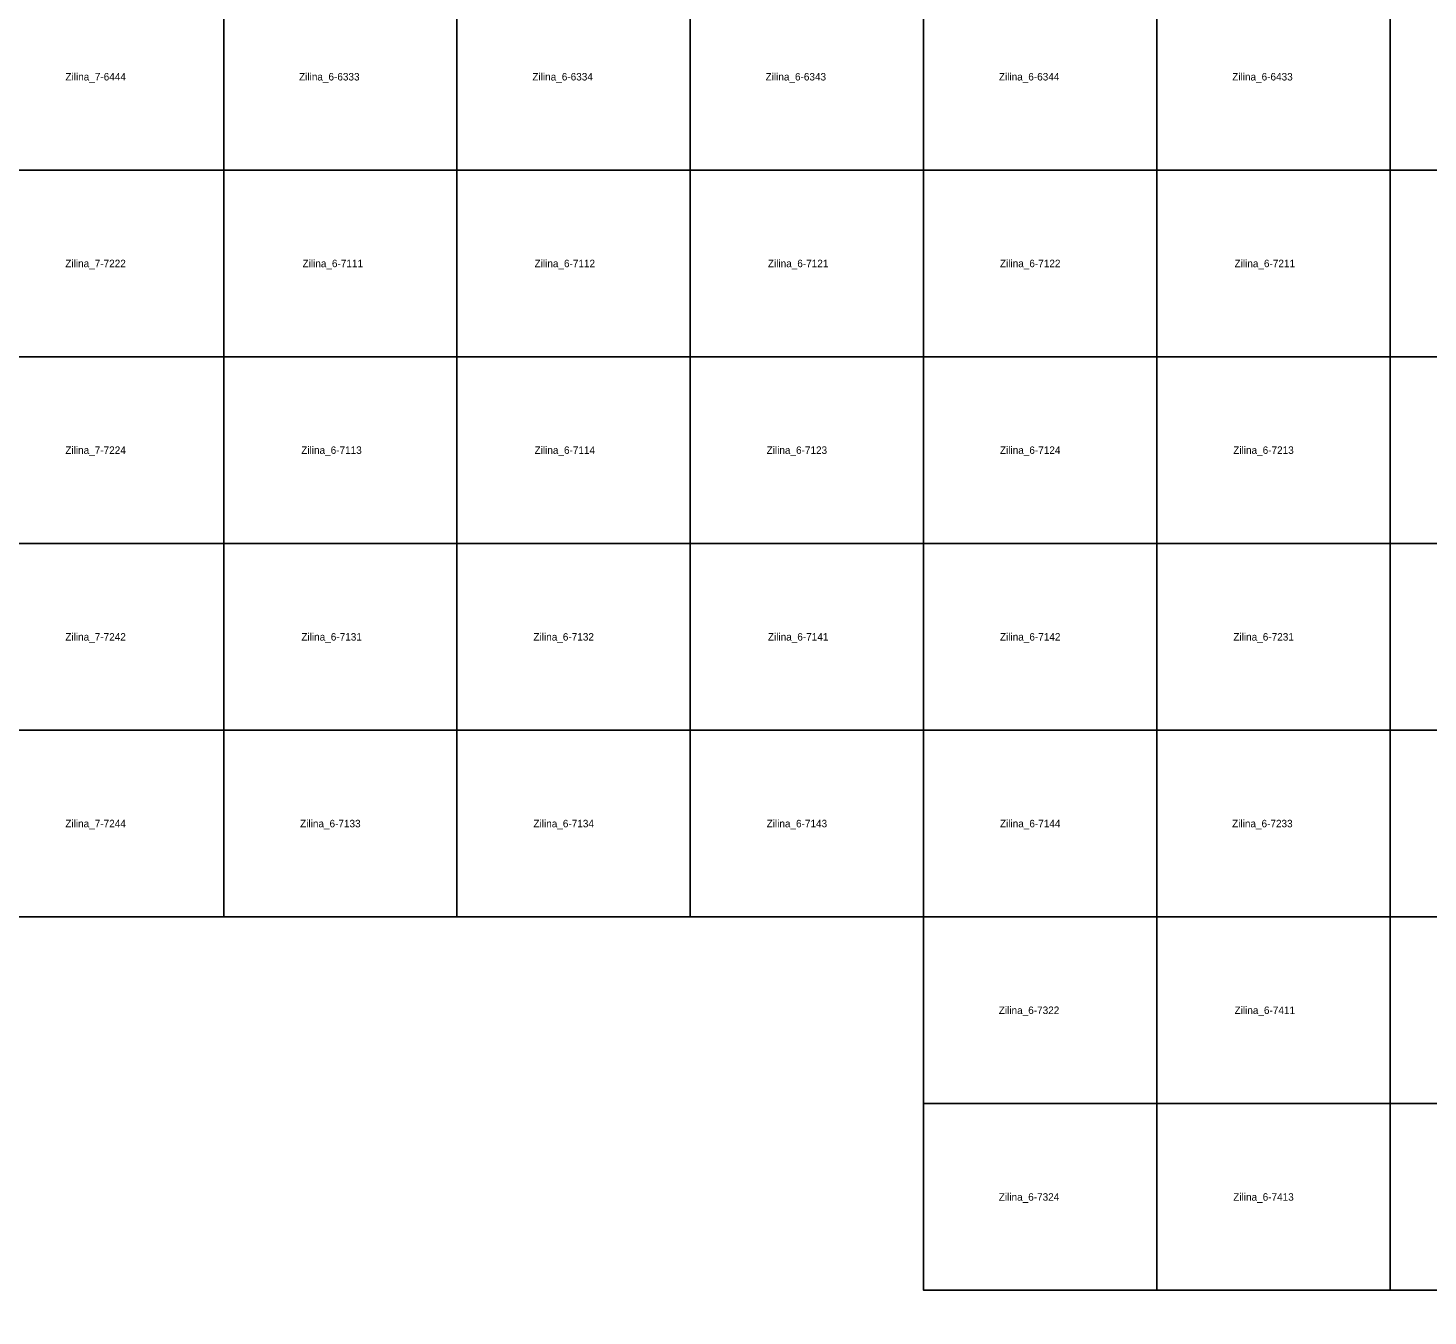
# Model space of a CAD drawing. Extents: x -445938 to -437812, y -1177250 to -1169500.
# Drawn here: x -442762 to -440887, y -1175534 to -1173810 of the extents above; entities that cross this region are included whole.
import ezdxf

# ---------------------------------------------------------------- set-up
doc = ezdxf.new("R2010")
doc.units = 0
for name, color, linetype in [('Vrstva 1', 7, 'Continuous'), ('Vrstva 4', 7, 'Continuous'), ('Vrstva 6', 7, 'Continuous')]:
    doc.layers.add(name, color=color, linetype=linetype)

msp = doc.modelspace()

# ---------------------------------------------------------------- linework, layer by layer
at = {"layer": 'Vrstva 1'}
msp.add_lwpolyline([(-440625, -1175500), (-441562.5, -1175500), (-441562.5, -1175000), (-442812.5, -1175000), (-442812.5, -1175750), (-443437.5, -1175750), (-443437.5, -1177250), (-445000, -1177250), (-445000, -1175500), (-445312.5, -1175500), (-445312.5, -1173750), (-445937.5, -1173750), (-445937.5, -1172250), (-445625, -1172250), (-445625, -1169500), (-444062.5, -1169500), (-444062.5, -1169750), (-441562.5, -1169750), (-441562.5, -1170000), (-440000, -1170000)], dxfattribs=at)
at = {"layer": 'Vrstva 4'}
for points in [[(-442500, -1173750), (-442500, -1174000), (-442812.5, -1174000), (-442812.5, -1173750)], [(-442187.5, -1173750), (-442187.5, -1174000), (-442500, -1174000), (-442500, -1173750)], [(-441875, -1173750), (-441875, -1174000), (-442187.5, -1174000), (-442187.5, -1173750)], [(-441562.5, -1173750), (-441562.5, -1174000), (-441875, -1174000), (-441875, -1173750)], [(-441250, -1173750), (-441250, -1174000), (-441562.5, -1174000), (-441562.5, -1173750)], [(-440937.5, -1173750), (-440937.5, -1174000), (-441250, -1174000), (-441250, -1173750)], [(-440625, -1173750), (-440625, -1174000), (-440937.5, -1174000), (-440937.5, -1173750)], [(-442500, -1174000), (-442500, -1174250), (-442812.5, -1174250), (-442812.5, -1174000)], [(-442187.5, -1174000), (-442187.5, -1174250), (-442500, -1174250), (-442500, -1174000)], [(-441875, -1174000), (-441875, -1174250), (-442187.5, -1174250), (-442187.5, -1174000)], [(-441562.5, -1174000), (-441562.5, -1174250), (-441875, -1174250), (-441875, -1174000)], [(-441250, -1174000), (-441250, -1174250), (-441562.5, -1174250), (-441562.5, -1174000)], [(-440937.5, -1174000), (-440937.5, -1174250), (-441250, -1174250), (-441250, -1174000)], [(-440625, -1174000), (-440625, -1174250), (-440937.5, -1174250), (-440937.5, -1174000)], [(-442500, -1174250), (-442500, -1174500), (-442812.5, -1174500), (-442812.5, -1174250)], [(-442187.5, -1174250), (-442187.5, -1174500), (-442500, -1174500), (-442500, -1174250)], [(-441875, -1174250), (-441875, -1174500), (-442187.5, -1174500), (-442187.5, -1174250)], [(-441562.5, -1174250), (-441562.5, -1174500), (-441875, -1174500), (-441875, -1174250)], [(-441250, -1174250), (-441250, -1174500), (-441562.5, -1174500), (-441562.5, -1174250)], [(-440937.5, -1174250), (-440937.5, -1174500), (-441250, -1174500), (-441250, -1174250)], [(-440625, -1174250), (-440625, -1174500), (-440937.5, -1174500), (-440937.5, -1174250)], [(-442500, -1174500), (-442500, -1174750), (-442812.5, -1174750), (-442812.5, -1174500)], [(-442187.5, -1174500), (-442187.5, -1174750), (-442500, -1174750), (-442500, -1174500)], [(-441875, -1174500), (-441875, -1174750), (-442187.5, -1174750), (-442187.5, -1174500)], [(-441562.5, -1174500), (-441562.5, -1174750), (-441875, -1174750), (-441875, -1174500)], [(-441250, -1174500), (-441250, -1174750), (-441562.5, -1174750), (-441562.5, -1174500)], [(-440937.5, -1174500), (-440937.5, -1174750), (-441250, -1174750), (-441250, -1174500)], [(-440625, -1174500), (-440625, -1174750), (-440937.5, -1174750), (-440937.5, -1174500)], [(-442500, -1174750), (-442500, -1175000), (-442812.5, -1175000), (-442812.5, -1174750)], [(-442187.5, -1174750), (-442187.5, -1175000), (-442500, -1175000), (-442500, -1174750)], [(-441875, -1174750), (-441875, -1175000), (-442187.5, -1175000), (-442187.5, -1174750)], [(-441562.5, -1174750), (-441562.5, -1175000), (-441875, -1175000), (-441875, -1174750)], [(-441250, -1174750), (-441250, -1175000), (-441562.5, -1175000), (-441562.5, -1174750)], [(-440937.5, -1174750), (-440937.5, -1175000), (-441250, -1175000), (-441250, -1174750)], [(-440625, -1174750), (-440625, -1175000), (-440937.5, -1175000), (-440937.5, -1174750)], [(-441250, -1175000), (-441250, -1175250), (-441562.5, -1175250), (-441562.5, -1175000)], [(-440937.5, -1175000), (-440937.5, -1175250), (-441250, -1175250), (-441250, -1175000)], [(-440625, -1175000), (-440625, -1175250), (-440937.5, -1175250), (-440937.5, -1175000)], [(-441250, -1175250), (-441250, -1175500), (-441562.5, -1175500), (-441562.5, -1175250)], [(-440937.5, -1175250), (-440937.5, -1175500), (-441250, -1175500), (-441250, -1175250)], [(-440625, -1175250), (-440625, -1175500), (-440937.5, -1175500), (-440937.5, -1175250)]]:
    msp.add_lwpolyline(points, close=True, dxfattribs=at)

# ---------------------------------------------------------------- texts
at = {"layer": 'Vrstva 6'}
for s, p in [('Zilina_7-6444', (-442711.954, -1173880)), ('Zilina_6-6333', (-442399.021, -1173880)), ('Zilina_6-6334', (-442086.521, -1173880)), ('Zilina_6-6343', (-441774.178, -1173880)), ('Zilina_6-6344', (-441461.678, -1173880)), ('Zilina_6-6433', (-441149.178, -1173880)), ('Zilina_7-7222', (-442712.072, -1174130)), ('Zilina_6-7111', (-442394.376, -1174130)), ('Zilina_6-7112', (-442083.568, -1174130)), ('Zilina_6-7121', (-441771.068, -1174130)), ('Zilina_6-7122', (-441460.261, -1174130)), ('Zilina_6-7211', (-441146.068, -1174130)), ('Zilina_7-7224', (-442712.072, -1174380)), ('Zilina_6-7113', (-442396.068, -1174380)), ('Zilina_6-7114', (-442083.568, -1174380)), ('Zilina_6-7123', (-441772.761, -1174380)), ('Zilina_6-7124', (-441460.261, -1174380)), ('Zilina_6-7213', (-441147.761, -1174380)), ('Zilina_7-7242', (-442712.072, -1174630)), ('Zilina_6-7131', (-442395.91, -1174630)), ('Zilina_6-7132', (-442085.104, -1174630)), ('Zilina_6-7141', (-441771.068, -1174630)), ('Zilina_6-7142', (-441460.261, -1174630)), ('Zilina_6-7231', (-441147.603, -1174630)), ('Zilina_7-7244', (-442712.072, -1174880)), ('Zilina_6-7133', (-442397.604, -1174880)), ('Zilina_6-7134', (-442085.104, -1174880)), ('Zilina_6-7143', (-441772.761, -1174880)), ('Zilina_6-7144', (-441460.261, -1174880)), ('Zilina_6-7233', (-441149.296, -1174880)), ('Zilina_6-7322', (-441461.796, -1175130)), ('Zilina_6-7411', (-441146.068, -1175130)), ('Zilina_6-7324', (-441461.796, -1175380)), ('Zilina_6-7413', (-441147.761, -1175380))]:
    msp.add_text(s, height=10, dxfattribs=at).set_placement(p)

doc.saveas('drawing.dxf')
